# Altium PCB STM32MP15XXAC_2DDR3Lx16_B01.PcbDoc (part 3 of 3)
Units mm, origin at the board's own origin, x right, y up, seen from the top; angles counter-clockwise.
Board outline 89 x 120 mm, 4 copper layers (Top Layer, Signal Layer 1, Signal Layer 2, Bottom Layer), stack 1.571 mm thick; 152 components, 117 nets, 1047 pads, 460 vias.
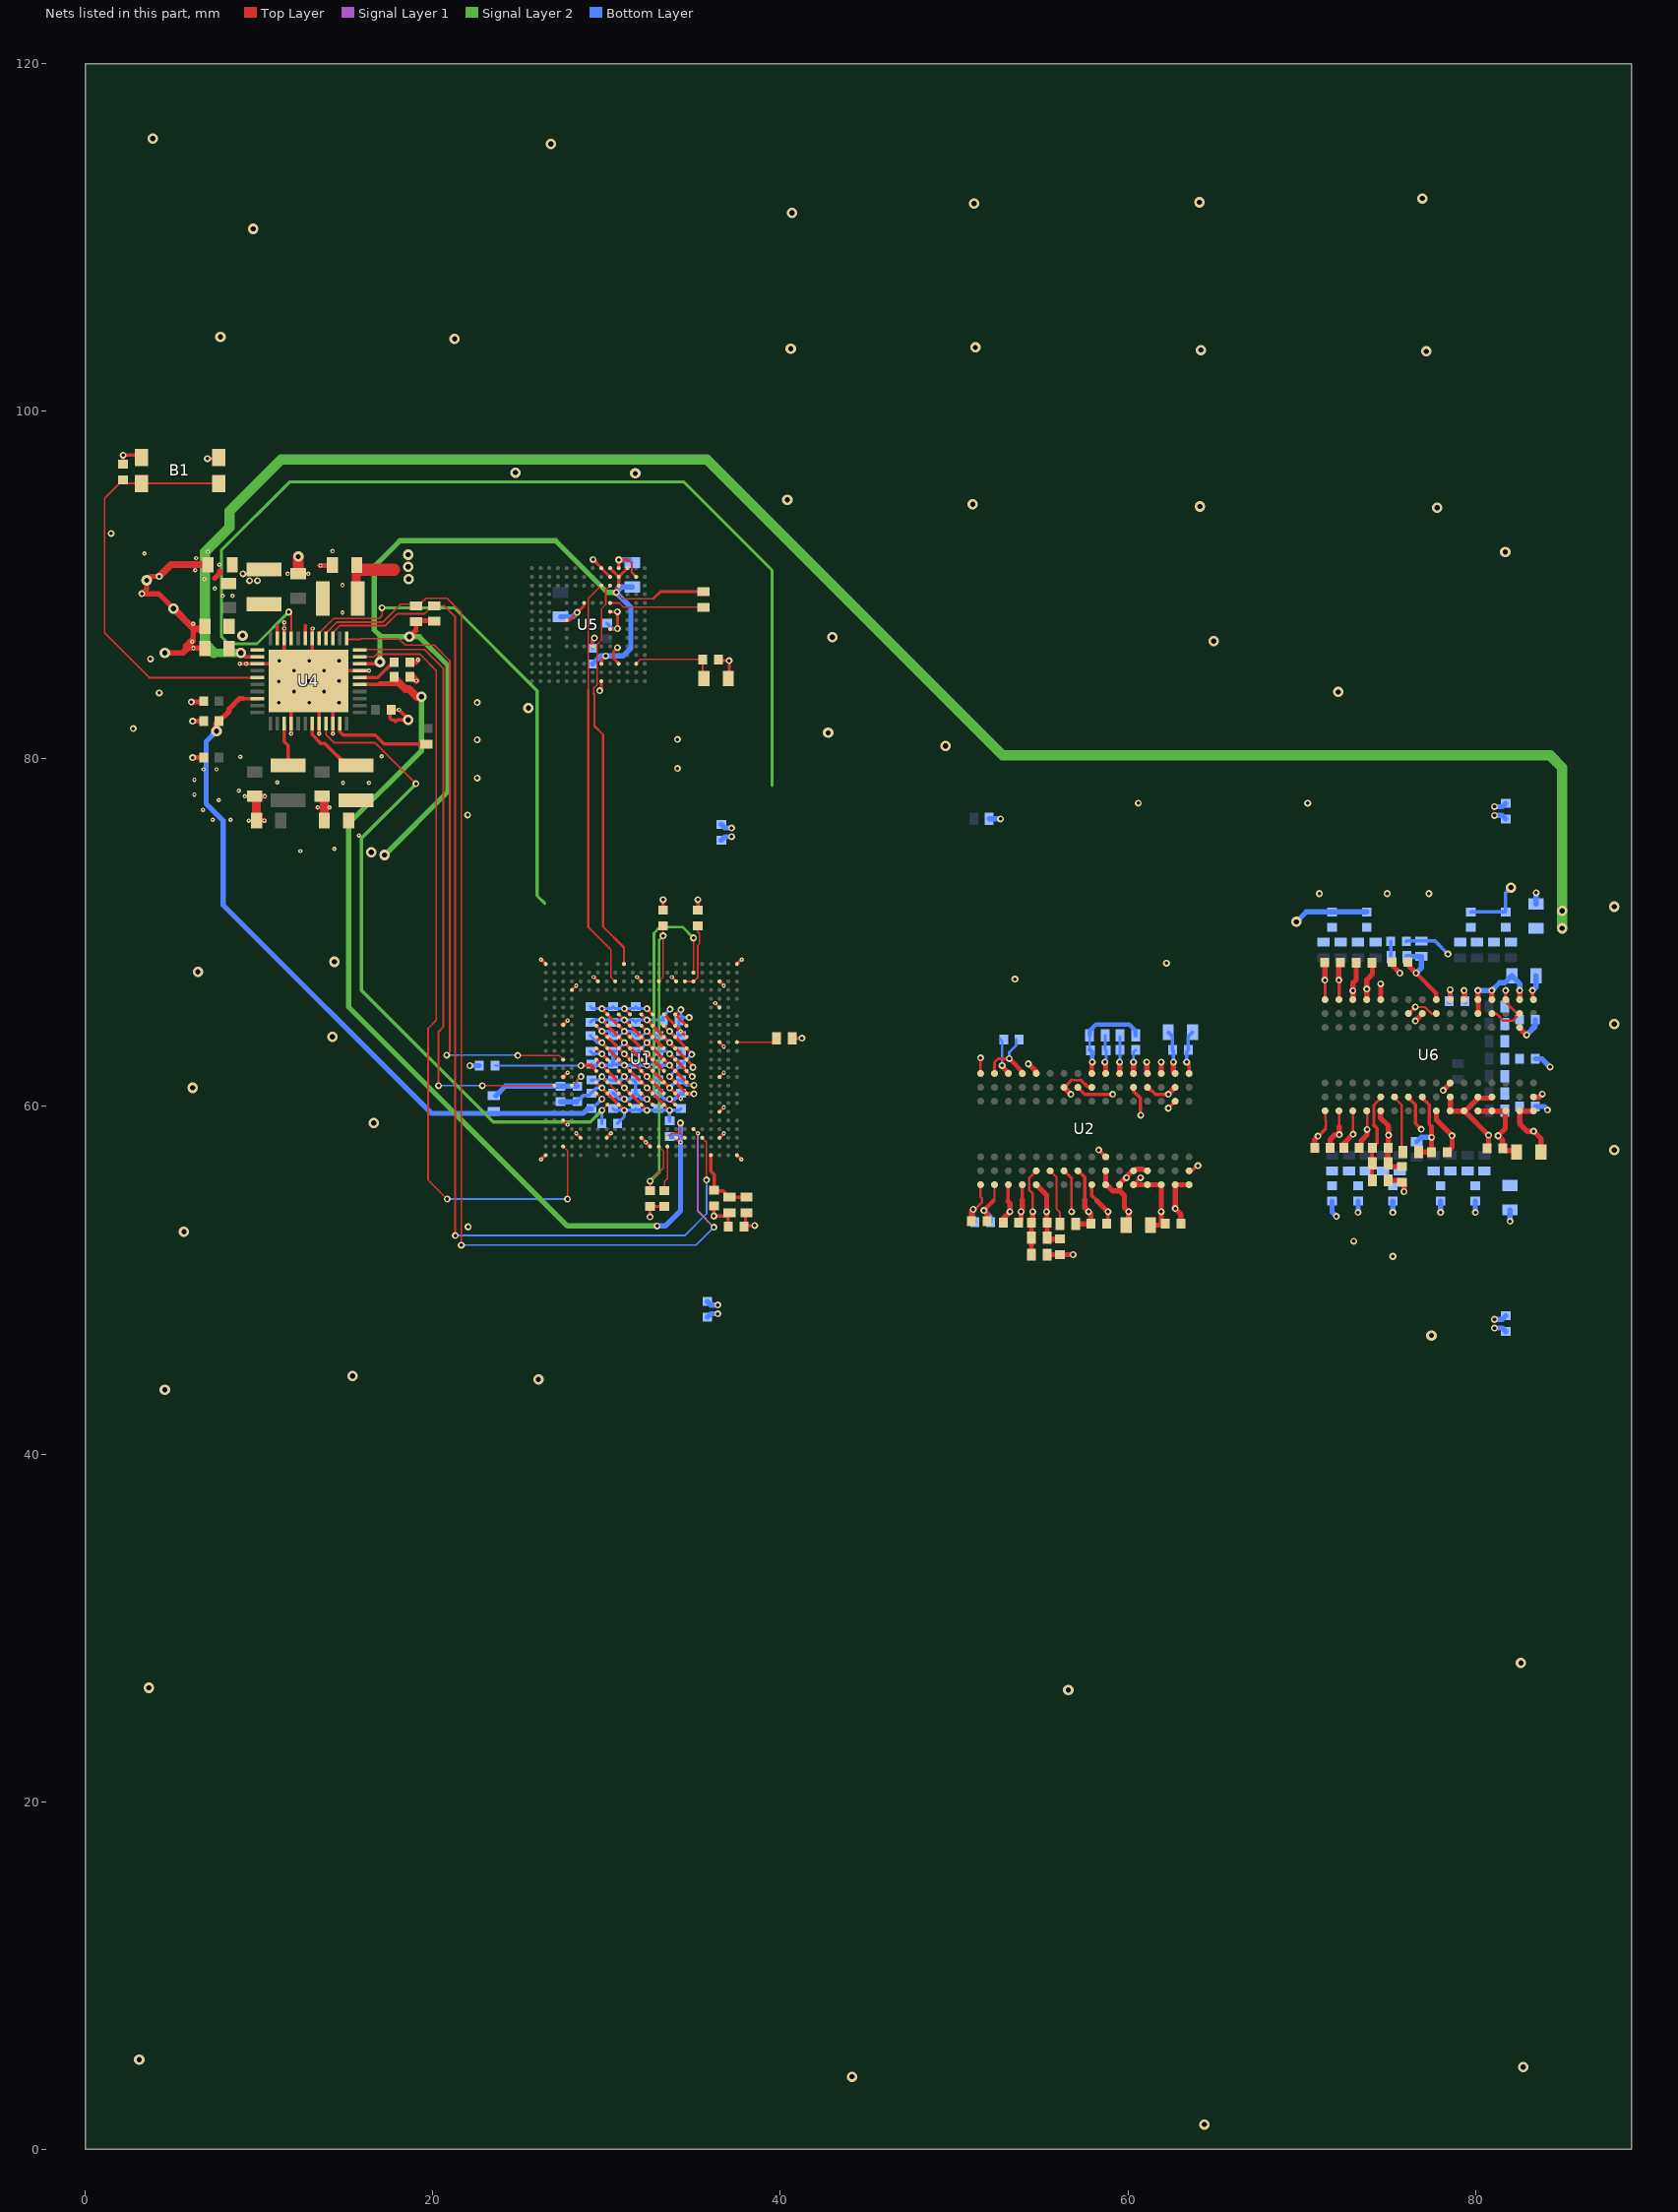
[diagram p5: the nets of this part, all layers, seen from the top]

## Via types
v1: diameter 0.4, hole 0.2, Top Layer to Bottom Layer, tented both sides, 302 vias
v2: diameter 0.6, hole 0.3, Top Layer to Bottom Layer, tented both sides, 80 vias
v3: diameter 0.25, hole 0.1, Top Layer to Signal Layer 1, tented top, 70 vias
v4: diameter 0.25, hole 0.1, Top Layer to Signal Layer 1, tented both sides, 6 vias
v5: diameter 0.25, hole 0.1, Top Layer to Bottom Layer, tented top, 2 vias

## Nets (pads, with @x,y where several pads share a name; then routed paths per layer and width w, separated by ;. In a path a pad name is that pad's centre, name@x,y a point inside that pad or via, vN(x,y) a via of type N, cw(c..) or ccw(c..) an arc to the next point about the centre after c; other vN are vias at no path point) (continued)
GND: B1.1 B1.2 C1.2 C2.2 C3.2 C4.2 C5.2 C6.2 C7.2 C8.2 C9.2 C10.2 C11.2 C12.2 C13.1 C14.1 C15.1 C16.1 C17.2 C18.1 C19.2 C20.2 C21.2 C22.2 C23.2 C24.2 C25.2 C26.2 C27.2 C28.2 C29.1 C30.1 C31.1 C32.1 C33.1 C34.1 C35.1 C36.1 C37.1 C38.1 C39.1 C40.1 C41.1 C42.1 C43.2 C44.1 C45.1 C46.1 C47.1 C48.1 C49.1 C50.1 C51.1 C52.1 C53.1 C54.1 C55.1 C56.1 C57.1 C58.1 C59.1 C60.2 C61.1 C62.2 C63.2 C64.2 C65.2 C66.1 C67.1 C68.1 C69.1 C70.1 C71.1 C72.1 C73.2 C74.2 C75.1 C76.1 C77.1 C78.1 C79.1 C80.1 C81.1 C82.1 C83.1 C84.2 C85.2 C86.2 C87.2 C88.1 C89.2 C90.2 C91.2 C92.1 C93.2 C94.1 C95.1 C96.1 C97.1 R26.1 R27.2 R28.1 R29.1 R30.1 R32.1 R42.1 R44.1 R45.1 R46.1 U1.1A3 U1.1A5 U1.1A7 U1.1B2 U1.1B4 U1.1B6 U1.1B8 U1.1C1 U1.1C3 U1.1C5 U1.1C7 U1.1C9 U1.1D2 U1.1D4 U1.1D6 U1.1D8 U1.1E1 U1.1E3 U1.1E5 U1.1E7 U1.1E9 U1.1F2 U1.1F4 U1.1F6 U1.1F8 U1.1G1 U1.1G3 U1.1G5 U1.1G7 U1.1G9 U1.1H2 U1.1H4 U1.1H6 U1.1H8 U1.1J3 U1.1J5 U1.1J7 U1.A1 U1.A23 U1.AA5 U1.AA8 U1.AA12 U1.AA16 U1.AA21 U1.AB13 U1.AC1 U1.AC23 U1.C7 U1.C12 U1.C16 U1.C21 U1.D4 U1.F21 U1.H3 U1.K21 U1.P3 U1.P21 U1.V21 U1.W3 U2.A9 U2.B1 U2.B3 U2.B9 U2.D1 U2.D8 U2.E1 U2.E2 U2.E8 U2.F9 U2.G1 U2.G8 U2.G9 U2.J2 U2.J8 U2.M1 U2.M9 U2.P1 U2.P9 U2.T1 U2.T9 U4.6 U4.10 U4.15 U4.26 U4.30 U4.32 U4.41 U4.ep U5.A6 U5.C4 U5.E7 U5.G5 U5.H10 U5.J5 U5.K8 U5.N2 U5.N5 U5.P4 U5.P6 U6.A9 U6.B1 U6.B3 U6.B9 U6.D1 U6.D8 U6.E1 U6.E2 U6.E8 U6.F9 U6.G1 U6.G8 U6.G9 U6.J2 U6.J8 U6.M1 U6.M9 U6.P1 U6.P9 U6.T1 U6.T9 | length 236.5
  Top Layer w0.09: 31.225,91.45 31.45,91.225 31.45,90.725
  Top Layer w0.12: U2.M1@54.725,61.9 U2.M1@54.725,62 ; v1(58.675,62.55) v1@58.725,62.5 ; v1@62.325,59.958 v1@62.383,59.958
  Top Layer w0.15: v1(51.105,54.08) 51.205,54.08 51.6,54.475 51.6,54.725 51.525,54.8 U2.T9@51.525,55.5 U2.T9@51.525,55.55 ; U2.T1@51.525,61.9 v1(51.525,62.8) ; v1@52.765,62.31 v1(52.765,62.36) ; v1(70.94,58.295) v1@70.975,58.295 ; U6.T1@71.36,66.085 71.36,66.15 v1@71.36,67.275 ; 71.375,58.695 71.375,58.845 71.4,58.87 71.4,59.18 71.375,59.205 U6.T9@71.375,59.75 ; v1(72.96,58.405) U6.P9@72.96,59.685 ; U6.T9@71.35,59.725 71.365,59.71 U6.T9@71.35,59.725
  Top Layer w0.175: v3(26.225,56.95) 26.475,57.2 U1.AC1@26.5,57.2 ; v3(26.225,68.45) 26.25,68.45 U1.A1@26.5,68.2 ; U1.W3@27.5,59.2 v3(27.75,58.95) ; U1.P3@27.5,61.7 v3(27.75,61.95) ; U5.H10@27.7,87.975 27.85,87.975 v1(28.3,88.425) 28.7,88.825 U5.K8@28.7,88.975 ; U1.D4@28,66.7 v3(28.25,66.95) ; v3(28.25,58.45) U1.AA5@28.5,58.2 ; v1(29.225,91.475) 29.7,91 U5.P6@29.7,90.975 U5.N5@30.2,90.475 ; v3(29.25,67.45) U1.C7@29.5,67.2 ; U1.1G1@29.4,61.4 v1(29.725,61.075) U1.1H2@30.05,60.75 U1.1J3@30.7,60.1 v1(31.025,59.775) ; U1.1E1@29.4,62.7 v1(29.725,62.375) U1.1F2@30.05,62.05 U1.1G3@30.7,61.4 v1(31.025,61.075) U1.1H4@31.35,60.75 U1.1J5@32,60.1 v1(32.325,59.775) ; U1.1C1@29.4,64 v1(29.725,63.675) U1.1D2@30.05,63.35 U1.1E3@30.7,62.7 v1(31.025,62.375) U1.1F4@31.35,62.05 U1.1G5@32,61.4 v1(32.325,61.075) U1.1H6@32.65,60.75 U1.1J7@33.3,60.1 v1(33.625,59.775) ; v1(29.6,83.925) 29.7,84.025 U5.A6@29.7,84.475 ; v1(29.725,64.975) U1.1B2@30.05,64.65 U1.1C3@30.7,64 v1(31.025,63.675) U1.1D4@31.35,63.35 U1.1E5@32,62.7 v1(32.325,62.375) U1.1F6@32.65,62.05 U1.1G7@33.3,61.4 v1(33.625,61.075) U1.1H8@33.95,60.75 33.975,60.75 v3(34.275,60.45) ; U5.G5@30.2,87.475 30.601,87.475 v1(30.625,87.5) v1(30.625,88.475) U5.J5@30.2,88.475 ; v1(30.625,86.4) 30.4,86.175 30.4,85.775 U5.C4@30.7,85.475 ; U1.1A3@30.7,65.3 v1(31.025,64.975) U1.1B4@31.35,64.65 U1.1C5@32,64 v1(32.325,63.675) U1.1D6@32.65,63.35 U1.1E7@33.3,62.7 v1(33.625,62.375) U1.1F8@33.95,62.05 U1.1G9@34.6,61.4 34.775,61.225 v1(35.025,61.225) ; U5.P4@30.7,90.948 U5.P4@30.7,90.975 v1(30.7,91.45) 31.225,91.45 ; 31.45,90.725 U5.N2@31.7,90.475 ; v3(31.75,67.45) U1.C12@32,67.2 ; U1.1A5@32,65.3 v1(32.325,64.975) U1.1B6@32.65,64.65 U1.1C7@33.3,64 v1(33.625,63.675) U1.1D8@33.95,63.35 U1.1E9@34.6,62.7 34.975,62.325 v1(34.975,62.25) ; v1(32.5,53.65) C67.1@32.5,54.25 C69.1@33.325,54.25 ; U1.1A7@33.3,65.3 U1.1B8@33.95,64.65 v3(34.275,64.325) U1.1C9@34.6,64 ; v3(33.75,67.45) U1.C16@34,67.2 ; U1.1C9@34.6,63.975 U1.1C9@34.6,64 ; U1.1C9@34.625,64 U1.1C9@34.6,64 ; v3(36.25,65.95) U1.F21@36.5,65.7 ; C82.1@36.425,85.725 36.5,85.65 v1(37.05,85.65) 37.05,84.675 C83.1@37,84.625 ; U1.AA21@36.5,58.2 v3(36.75,58.45) ; U1.V21@36.5,59.7 v3(36.75,59.95) ; U1.P21@36.5,61.7 v3(36.75,61.95) ; U1.K21@36.5,63.7 v3(36.75,63.45) ; U1.C21@36.5,67.2 v3(36.75,66.95) ; U1.AC23@37.5,57.2 v3(37.75,56.95) ; U1.A23@37.5,68.2 37.75,68.45 v3(37.775,68.45)
  Top Layer w0.2: C44.1@2.175,96.95 v1(2.175,97.475) 3.1,97.475 B1.1@3.225,97.35 ; v1(7.025,97.275) 7.6,97.275 B1.2@7.675,97.35 ; v4(8.882,85.482) 9.243,85.482 v4(9.25,85.475) U4.15@9.9,85.475 10.875,85.475 U4.ep@10.9,85.45 ; v3@11.45,87.825 v3(11.45,87.5) U4.10@11.45,86.925 11.45,85.875 12.125,85.2 v1(12.85,84.475) ; v3(11.85,81.45) U4.26@11.85,82.025 11.85,83.475 12.125,83.75 v1(12.85,84.475) ; v2(12.255,91.64) v2@12.381,91.514 ; v3@13.05,87.5 U4.6@13.05,86.925 13.05,85.65 U4.ep@13.05,84.675 ; v3@13.45,81.425 v3(13.45,81.45) U4.30@13.45,82.025 U4.ep@13.45,83.875 ; v3(14.25,81.45) U4.32@14.25,82.025 14.25,83.075 13.587,83.738 U4.ep@13.45,83.875 ; v3(16.325,85.075) U4.41@15.8,85.075 v1(13.725,85.075) 13.45,85.075 U4.ep@13.05,84.675 ; C51.1@17.537,82.762 17.537,82.338 17.625,82.25 17.757,82.25 17.857,82.15 17.957,82.25 v2(18.575,82.25) ; C51.1@17.6,82.825 v3(18.05,82.825) v2@18.6,82.275 ; U1.H3@27.5,64.7 v3(27.75,64.95) ; U5.E7@29.2,86.475 29.2,86.825 29.312,86.937 v1@29.325,86.95 ; U1.AA8@30,58.2 v3(30.25,58.45) ; U1.AA12@32,58.2 v5(32.25,57.95) U1.AB13@32.5,57.7 ; C66.1@33.25,71.3 v1(33.25,71.9) ; U1.AA16@34,58.2 v3(34.25,57.95) ; C68.1@35.25,71.3 v1(35.25,71.9) ; C72.1@36,54.275 36.087,54.188 36.175,54.1 v1(36.175,53.7) 37,53.7 C88.1@37,53.1 C88.1@37,53.05 ; R27.2@40.675,63.925 v1(41.25,63.925) ; 53.105,54.53 53.105,55.48 U2.P9@53.125,55.5 ; C26.2@55.325,53.35 C26.2@55.35,53.325 ; R44.1@55.35,52.45 R44.1@55.425,52.375 ; U2.J8@57.105,56.343 57.136,56.311 57.525,55.923 57.525,54.625 ; U2.J2@57.125,61.1 57.525,60.7 v1(59.125,60.7) ; U2.E2@60.325,61.15 U2.E2@60.325,61.1 60.325,60.88 60.725,60.48 v1@60.725,59.5 ; U2.D1@61.085,61.94 U2.D1@61.125,61.9 ; v1(61.085,62.55) v1@61.125,62.51 ; v1@62.383,59.958 U2.B3@62.725,60.3 ; U2.B1@62.625,62 U2.B1@62.725,61.9 ; v1@70.975,58.295 71.375,58.695 ; R46.1@74.975,56.725 R46.1@75.15,56.55 ; C28.2@74.975,57.625 C28.2@75,57.65 ; C27.2@75.22,68.115 C27.2@75.22,68.315 ; U6.J8@76.96,60.485 77.34,60.105 77.34,58.96 77.48,58.82 ; U6.G9@78.55,59.725 U6.G9@78.56,59.725 ; U6.G1@78.55,66.125 U6.G1@78.55,66.15 v1(78.55,66.715) ; U6.F9@79.36,59.685 79.387,59.713 79.39,59.715 U6.F9@79.38,59.725 ; C60.2@80.76,57.525 C60.2@80.82,57.465 ; U6.A9@83.32,59.725 83.323,59.723 U6.A9@83.37,59.675 ; C58.1@83.775,57.46 83.818,57.418 C58.1@83.97,57.265 ; v1(12.85,84.475) U4.ep@13.05,84.675 ; v1(12.85,84.475) U4.ep@13.45,83.875
  Top Layer w0.3: v1(4.25,90.5) 3.75,90.5 v2(3.525,90.275) 3.525,89.775 v1(3.25,89.5) 4.225,89.5 v2(5.075,88.65) ; v2(4.575,86.1) 5.65,86.1 5.675,86.125 ; v1(6.1,83.275) 6.75,83.275 C41.1@6.8,83.325 C41.1@6.775,83.35 ; v3(6.144,86.744) 5.925,86.525 5.925,86.5 ; v1(6.175,80.075) C32.1@6.8,80.075 ; v1(6.175,82.175) C49.1@6.8,82.175 ; v3(6.2,87.775) 6.2,87.525 6.2,86.95 ; C46.1@6.85,86.375 v3(6.214,86.375) 5.925,86.375 ; 7.45,90.4 7.725,90.675 7.725,90.8 ; C39.1@9.75,77.85 v3(10.325,77.85) ; C40.1@9.85,76.45 v3(10.3,76.45) ; C33.1@12.255,90.701 12.25,90.696 12.227,90.673 C33.1@12.25,90.65 C33.1@12.4,90.5 ; v3@13.5,91.125 v3(13.525,91.125) 13.95,91.125 14.075,91 C34.1@14.2,90.875 ; C43.2@18.6,85.575 18.649,85.526 C43.2@18.65,85.525 ; C43.2@18.684,85.562 19.012,85.562 v3(19.15,85.7) ; C21.2@51,53.4 51,53.975 v1(51.105,54.08) ; v1@52.765,62.31 U2.P1@53.15,61.925 ; C20.2@52.825,53.325 52.825,53.56 v1(53.215,53.95) 53.215,54.42 53.105,54.53 ; v1(54.275,62.45) U2.M1@54.725,62 ; U2.M9@54.725,55.5 55.325,54.9 v1(55.325,53.95) C26.2@55.325,53.35 ; R44.1@55.35,52.45 C26.2@55.35,53.325 ; R44.1@55.425,52.375 C90.2@56.1,52.375 ; R29.1@57,53.25 C19.2@57.875,53.25 57.875,53.81 57.74,53.945 57.525,54.16 57.525,54.625 ; U2.G9@58.725,55.5 U2.G9@58.725,55.55 ; U2.G8@58.725,56.3 U2.G9@58.725,55.55 ; U2.G1@58.725,61.9 v1@58.725,62.5 ; U2.F9@59.505,55.543 59.894,55.931 60.294,56.331 60.305,56.343 60.325,56.343 60.438,56.343 60.489,56.393 60.861,56.393 60.912,56.343 U2.D8@61.053,56.343 ; U2.F9@59.525,55.55 U2.F9@59.525,55.5 59.525,55.15 ; C15.1@59.9,53.175 60.045,53.32 60.045,53.93 60.035,53.94 59.805,54.17 59.805,54.87 59.525,55.15 ; U2.E1@60.325,61.9 v1(60.325,62.55) ; U2.D1@61.085,61.94 v1(61.085,62.55) ; U2.B1@62.625,62 v1(62.625,62.55) ; C17.2@63.05,53.25 63.05,53.8 v1(62.725,54.125) U2.B9@62.725,55.5 U2.A9@63.525,55.5 ; C74.2@70.75,57.625 70.75,58.105 v1(70.94,58.295) ; v1(71.34,67.275) C63.2@71.34,68.285 ; C73.2@72.425,57.625 72.425,57.87 v1(72.96,58.405) ; U6.P1@72.95,66.125 U6.P1@72.95,66.15 v1(72.95,66.665) 72.95,67.105 73.14,67.295 C65.2@73.14,68.275 ; U6.M9@74.55,59.725 74.55,59.33 75,58.88 v1(75,58.345) C28.2@75,57.65 ; U6.M1@74.56,66.125 74.56,66.15 v1@74.56,67.055 ; R46.1@74.975,56.725 C28.2@74.975,57.625 ; R46.1@75.15,56.55 C93.2@75.775,56.55 ; C27.2@75.22,68.115 v1(75.66,67.675) ; v1(76.55,64.925) U6.J2@76.95,65.325 ; R30.1@76.725,57.375 C62.2@77.475,57.375 ; C62.2@77.48,57.375 v1(77.48,58.225) 77.48,58.82 ; U6.G8@78.56,60.485 78.56,59.75 78.56,59.725 79.35,59.725 U6.F9@79.38,59.725 ; U6.E1@80.15,66.125 U6.E1@80.15,66.15 v1(80.15,66.675) ; U6.E2@80.16,65.325 80.16,65.35 U6.E1@80.16,66.125 ; C60.2@80.76,57.525 80.76,57.6 v1(80.76,58.345) 79.39,59.715 80.16,60.485 80.95,60.485 U6.D8@80.96,60.485 ; U6.D1@80.95,66.125 U6.D1@80.95,66.15 v1(80.95,66.675) ; U6.B3@82.55,64.51 v1(82.945,64.115) ; U6.B1@82.55,66.125 U6.B1@82.55,66.15 v1(82.55,66.675) ; U6.A9@83.32,59.725 82.55,59.725 82.55,59.005 82.98,58.575 v1(83.35,58.575) 83.775,58.15 C58.1@83.775,57.46 ; 5.675,86.125 5.675,86.25 5.863,86.438 ; 5.675,86.125 5.925,86.375 ; 5.863,86.438 5.925,86.5 ; 5.863,86.438 5.925,86.375 ; 5.863,86.438 5.775,86.525 6.069,86.819 6.2,86.95 ; 5.925,86.375 5.925,86.5 ; 5.925,86.5 6.157,86.732 6.2,86.775 6.2,86.95 ; U2.G9@58.725,55.55 58.75,55.525 59.125,55.15 59.525,55.15
  Top Layer w0.4: v1(4.25,90.5) 4.925,91.175 6.325,91.175 C29.1@7.05,91.175 ; v2(5.075,88.65) 6.075,87.65 6.2,87.525 6.25,87.475 C42.1@6.6,87.475 ; C52.1@18.751,84.801 v3(19.053,84.5)
  Top Layer w0.5: C18.1@8.125,90.1 C18.1@8.25,90.1 ; C39.1@9.75,77.85 9.85,77.75 C40.1@9.85,76.45 ; C31.1@13.625,77.85 13.625,77.75 13.75,77.625 13.75,77.2 C38.1@13.75,76.45
  Top Layer w0.6: C33.1@12.25,90.65 12.25,90.696 12.25,91.635 v2(12.255,91.64)
  Bottom Layer w0.15: C22.2@52.675,63.85 52.762,63.762 52.765,63.76 v1(52.765,62.36) ; v1(58.675,62.55) 58.75,62.625 C25.2@58.75,63.225 58.7,63.275 R42.1@58.7,64.1 ; v1(60.325,62.55) 60.325,63.125 C89.2@60.45,63.25
  Bottom Layer w0.175: C75.1@29.075,64.075 29.475,63.675 v1(29.725,63.675) 30.225,63.175 C37.1@30.375,63.175 30.525,63.175 v1(31.025,63.675) 31.525,63.175 C36.1@31.675,63.175 31.825,63.175 v1(32.325,63.675) 32.725,64.075 C45.1@32.975,64.075 33.225,64.075 v1(33.625,63.675) 34.125,63.175 C57.1@34.275,63.175 ; C35.1@29.075,64.85 29.2,64.975 v1(29.725,64.975) 30.375,64.975 v1(31.025,64.975) 31.55,64.975 C76.1@31.675,64.85 31.8,64.975 v1(32.325,64.975) C53.1@33.25,64.975 ; C96.1@30.375,59.875 C96.1@30.475,59.775 ; C47.1@30.625,59.025 31.025,59.425 v1(31.025,59.775) ; C81.1@31.325,91.45 C81.1@31.475,91.3 ; C95.1@31.575,59.775 C95.1@31.675,59.875 C95.1@31.775,59.775 ; C55.1@32.875,59.775 C55.1@32.975,59.875 C55.1@33.075,59.775 ; C53.1@33.275,64.95 C53.1@33.25,64.975 ; v1(33.65,65.6) 33.25,65.2 C53.1@33.25,64.975 ; C54.1@34.175,59.775 C54.1@34.275,59.875
  Bottom Layer w0.2: C97.1@28.3,60.35 28.3,60.275 28.312,60.287 28.65,60.625 28.975,60.625 C70.1@29.125,60.775 29.425,61.075 v1(29.725,61.075) ; C94.1@29.125,62.425 29.175,62.375 v1(29.725,62.375) 30.325,62.375 C48.1@30.375,62.425 ; C80.1@29.2,86.375 29.2,86.825 29.312,86.937 v1@29.325,86.95 ; C78.1@30.025,87.8 30.35,87.475 30.6,87.475 v1(30.625,87.5) ; C37.1@30.375,63.175 C48.1@30.375,62.425 ; C96.1@30.475,59.775 v1(31.025,59.775) C95.1@31.575,59.775 ; C92.1@31.675,62.425 C92.1@31.725,62.375 ; C95.1@31.775,59.775 v1(32.325,59.775) C55.1@32.875,59.775 ; C55.1@33.075,59.775 v1(33.625,59.775) ; C71.1@33.625,59.175 v1(33.625,59.775) ; v1(33.625,61.075) 34.075,61.525 C56.1@34.275,61.525 34.575,61.225 v1(35.025,61.225) ; v1(33.625,62.375) 33.025,62.375 C77.1@32.975,62.425 32.375,62.425 v1(32.325,62.375) C92.1@31.725,62.375 ; C54.1@34.175,59.775 v1(33.625,59.775) ; v1(51.105,54.08) 51.105,53.445 C23.2@51.2,53.35 ; C16.1@62.325,64.275 62.575,64.025 C24.2@62.575,63.25 62.625,63.2 v1(62.625,62.55) ; C91.2@75.125,69.5 75.125,68.625 R45.1@75.15,68.6 75.15,68.185 v1(75.66,67.675) ; C10.2@79.75,71.2 C9.2@81.75,71.2 81.75,72.3 v2(82.05,72.6) ; C48.1@30.375,62.425 30.975,62.425 v1(31.025,62.375) 31.675,62.375 C92.1@31.725,62.375
  Bottom Layer w0.3: v1(22.125,62.35) C61.1@22.675,62.35 ; C50.1@27.35,60.275 C97.1@28.3,60.275 ; C79.1@27.35,88.175 28.05,88.175 v1(28.3,88.425) ; v1(30.7,91.45) C81.1@31.325,91.45 ; C87.2@35.8,48.775 36,48.575 v1(36.4,48.575) ; C84.2@36.6,76.225 36.8,76.025 v1(37.2,76.025) ; R28.1@52.025,76.55 v1(52.675,76.55) ; v2(69.7,70.625) 70.275,71.2 C12.2@71.75,71.2 C11.2@73.75,71.2 ; C2.2@71.75,54.55 71.75,53.925 v1(72,53.675) ; v1(73.25,53.9) C3.2@73.25,54.55 ; v1(75.25,53.9) C4.2@75.25,54.55 ; R26.1@76.625,57.975 76.875,58.225 v1(77.48,58.225) ; v1(78,53.9) C1.2@78,54.55 ; C64.2@78.5,66.05 78.55,66.1 v1(78.55,66.715) ; v1(80,53.9) C5.2@80,54.55 ; v1(80.15,66.675) v1(80.95,66.675) 81.4,67.125 81.7,67.125 C59.1@82.1,67.525 82.55,67.075 v1(82.55,66.675) ; v1(81.1,47.75) 81.55,47.75 C86.2@81.75,47.95 ; v1(81.1,77.25) 81.55,77.25 C85.2@81.75,77.45 ; v1(82,53.4) C13.1@82,54.05 ; v1(82.945,64.115) 83.45,64.62 C8.2@83.45,65 ; C6.2@83.45,60 83.95,60 v1(84.15,59.8) ; C7.2@83.45,62.75 83.825,62.75 v1(84.3,62.275) ; C14.1@83.5,71.65 v1(83.5,72.3)
  other v1: 75.25,51.375 73,52.25 22.025,53.075 57.745,53.95 60.045,53.95 59.925,55.9 60.745,59.5 62.325,59.9 74.55,67.055 53.5,67.325 62.225,68.25 71.025,72.25 74.925,72.25 77.325,72.25 22,76.775 60.6,77.45 70.35,77.45 22.55,78.9 34.075,79.45 22.55,81.1 34.075,81.125 2.75,81.75 11.125,83.225 12.875,83.225 14.6,83.225 22.55,83.25 4.25,83.801 12,83.875 13.725,83.875 11.125,84.45 14.6,84.475 12,85.075 11.15,85.65 12.875,85.65 14.6,85.65 3.75,85.75 29.3,86.95 1.475,92.975
  other v2: 64.4,1.425 44.125,4.175 82.75,4.725 3.1,5.15 56.575,26.425 3.65,26.55 82.625,27.975 4.575,43.7 26.075,44.3 15.375,44.5 77.475,46.825 5.675,52.8 88,57.5 16.6,59.05 6.175,61.075 14.225,64 88,64.75 6.475,67.75 14.325,68.325 88,71.5 49.5,80.75 42.75,81.5 25.5,82.925 72.1,83.85 64.95,86.775 43,87 81.725,91.9 77.8,94.45 64.15,94.525 51.075,94.65 40.4,94.9 31.65,96.425 24.75,96.475 77.175,103.45 64.2,103.525 40.6,103.6 51.225,103.675 21.25,104.175 7.775,104.275 9.65,110.5 40.675,111.425 51.15,111.95 64.125,112.025 76.95,112.25 26.8,115.375 3.875,115.7
  other v3: 12.375,74.7 14.325,74.825 15.75,75.6 9.4,76.45 6.775,77.075 13.375,77.2 14.05,77.2 7.675,77.625 9.175,77.85 8.825,78.175 14.825,78.625 16.325,78.625 11.05,78.65 6.8,79.4 7.55,79.4 8.911,80.125 17.05,80.15 13.075,87.5 11.45,87.85 14.8,88.425 7.9,89.375 8.475,89.375 7.45,89.8 14.8,90 6.85,90.35 11.65,90.65 12.825,90.65 6.325,90.85 7.7,91.175 6.375,91.55 3.4,91.825 7.05,91.925 14.225,91.95
  other v4: 7.325,76.5 8.35,76.5 6.275,77.95 6.275,78.8
I2C4_SCL: R37.2 U1.Y18 U4.4 | length 66.8
  Top Layer w0.1: U4.4@13.85,86.925 13.85,87.237 14.488,87.875 17.125,87.875 18.15,88.9 19.025,88.9 19.26,88.9 19.6,89.24 20.81,89.24 21.638,88.413 v1(21.638,52.025) ; U1.Y18@35,58.7 v5(35.25,58.45)
  Signal Layer 1 w0.1: v5(35.25,58.45) 35.25,53.975 v1(36.175,53.05)
  Bottom Layer w0.1: v1(21.638,52.025) 35.15,52.025 v1(36.175,53.05)
I2C4_SDA: R38.2 U1.AA19 U4.3 | length 63.3
  Top Layer w0.09: U1.AA19@35.5,58.2 35.75,57.95 v1(35.75,55.775)
  Top Layer w0.1: U4.3@14.25,86.925 14.25,87.267 14.658,87.675 17.275,87.675 17.95,88.35 19.525,88.35 20.012,88.838 R38.2@19.975,88.875 ; R38.2@20.074,88.813 20.637,88.813 21.288,88.162 v1(21.288,52.575)
  Bottom Layer w0.1: v1(21.288,52.575) 34.5,52.575 35.75,53.825 v1(35.75,55.775)
NetB1_3: B1.3 B1.4 C44.2 U4.17 | length 24.5
  Top Layer w0.1: B1.4@7.675,95.85 B1.3@3.225,95.85 2.175,95.85 1.95,95.85 1.1,95 1.1,87.25 3.675,84.675 U4.17@9.9,84.675
NetC25_1: C25.1 R33.1 R42.2 U2.H1 | length 5.7
  Top Layer w0.25: U2.H1@57.925,61.9 57.925,62.52 v1(57.955,62.55)
  Bottom Layer w0.15: C25.1@57.8,63.275 R42.2@57.8,64.1
  Bottom Layer w0.25: C25.1@57.8,63.275 C25.1@57.85,63.225 57.955,63.12 v1(57.955,62.55) ; R42.2@57.8,64.1 57.8,64.35 58.175,64.725 60.075,64.725 60.45,64.35 R33.1@60.45,64.1
NetC26_1: C26.1 R34.1 R44.2 U2.M8 | length 5.1
  Top Layer w0.15: C26.1@54.45,53.325 C26.1@54.525,53.4 ; v1(54.525,53.95) v1@54.525,54.1 ; 54.525,54.15 54.525,54.975 54.325,55.175 54.325,55.9 U2.M8@54.725,56.3
  Top Layer w0.3: R34.1@54.45,51.475 R44.2@54.45,52.45 C26.1@54.45,53.325 ; C26.1@54.525,53.4 v1(54.525,53.95)
NetC27_1: C27.1 R35.1 R45.2 U6.H1 | length 4.8
  Top Layer w0.25: C27.1@76.12,68.145 C27.1@76.12,68.315 ; v1(76.59,67.675) 77.75,66.515 U6.H1@77.75,66.15 U6.H1@77.75,66.125
  Top Layer w0.3: C27.1@76.12,68.145 v1(76.59,67.675)
  Bottom Layer w0.3: R45.2@76.05,68.6 76.075,68.625 R35.1@76.9,68.625 76.9,67.985 v1(76.59,67.675)
NetC28_1: C28.1 R36.1 R46.2 U6.M8 | length 5.1
  Top Layer w0.15: 74.16,58.925 74.16,60.085 U6.M8@74.56,60.485
  Top Layer w0.2: R36.1@74.075,55.75 R46.2@74.075,56.725 C28.1@74.075,57.625 74.346,57.896 74.346,58.739 74.16,58.925 ; U6.M8@74.51,60.485 74.55,60.485 U6.M8@74.56,60.485
NetC43_1: C43.1 U4.40 | length 2.2
  Top Layer w0.2: U4.40@15.8,84.675 16.828,84.675 C43.1@17.689,85.536
NetC61_2: C61.2 U1.1F1 | length 6
  Top Layer w0.2: v1@28.55,62.375 29.075,62.375 U1.1F1@29.4,62.05
  Top Layer w0.3: v1@28.475,62.35 v1(28.525,62.35) v1@28.55,62.375
  Bottom Layer w0.1: C61.2@23.575,62.35 v1(28.525,62.35)
NetC68_2: C68.2 U1.C17 U1.C18 | length 3.9
  Top Layer w0.1: U1.C17@34.5,67.2 U1.C18@35,67.2 35.025,67.2 35.25,67.425 35.25,69.275 35.35,69.375 35.35,69.945 35.25,70.045 C68.2@35.25,70.4
NetC69_2: C69.2 U1.AB15 | length 2.6
  Top Layer w0.09: C69.2@33.325,55.15 33.325,55.675 33.5,55.85 U1.AB15@33.5,57.7
NetC72_2: C72.2 R31.1 R32.2 U1.AC20 | length 4.1
  Top Layer w0.2: U1.AC20@36,57.2 36,56.275 36.2,56.075 36.2,55.175 36.2,55.15 36.7,55.15 R32.2@37.075,54.775 R31.1@38.05,54.775
NetC82_2: C82.2 C83.2 U5.C2 | length 5.1
  Top Layer w0.09: U5.C2@31.7,85.475 31.95,85.725 32.7,85.725
  Top Layer w0.1: 32.7,85.725 C82.2@35.525,85.725 35.525,84.7 C83.2@35.6,84.625
NetL1_1: L1.1 U4.7 | length 0.7
  Top Layer w0.2: U4.7@12.65,86.925 12.65,87.672
NetL2_1: L2.1 U4.11 | length 0.7
  Top Layer w0.2: U4.11@11.05,86.925 11.05,87.65
NetL3_1: L3.1 U4.29 | length 3.9
  Top Layer w0.2: U4.29@13.05,82.025 13.05,81.39 13.565,80.875 13.8,80.875 15.05,79.625 L3.1@15.575,79.625
NetL4_1: L4.1 U4.25 | length 2.4
  Top Layer w0.2: U4.25@11.45,82.025 11.45,81 11.675,80.775 L4.1@11.675,79.725
NetR27_1: R27.1 U1.K23 | length 2.3
  Top Layer w0.09: U1.K23@37.5,63.7 39.75,63.7 R27.1@39.775,63.725
NetR29_2: R29.2 U2.L8 | length 3.3
  Top Layer w0.12: U2.L8@55.525,56.3 55.9,55.925 55.9,54.1 56.1,53.9 R29.2@56.1,53.25 R29.2@56.1,53.225
NetR30_2: R30.2 U6.L8 | length 3.3
  Top Layer w0.12: U6.L8@75.36,60.485 75.76,60.085 75.76,57.44 R30.2@75.825,57.375
NetR40_1: R40.1 U5.K5 | length 5.5
  Top Layer w0.09: 30.725,88.975 30.975,88.725 R40.1@35.575,88.725
  Top Layer w0.1: U5.K5@30.2,88.975 30.725,88.975
NetR43_1: R43.1 U4.33 | length 5.7
  Top Layer w0.2: U4.33@14.65,82.025 14.65,81.561 14.836,81.375 16.675,81.375 17.2,80.85 R43.1@19.625,80.85
NRST: U1.M3 U4.1 | length 36
  Top Layer w0.09: v1(24.89,62.94) 27.26,62.94 U1.M3@27.5,62.7
  Top Layer w0.1: U4.1@15.05,86.875 15.82,86.875 15.87,86.925 18.025,86.925 18.4,86.55 20.075,86.55 20.975,85.65 20.975,63.125 v1(20.8,62.95)
  Bottom Layer w0.09: v1(20.8,62.95) 24.88,62.95 v1(24.89,62.94)
PA0_WKUP: U1.AB3 U4.43 | length 46
  Top Layer w0.09: U1.AB3@27.5,57.7 27.75,57.45 v1(27.75,54.675)
  Top Layer w0.1: U4.43@15.8,85.875 16.614,85.875 16.764,86.025 19.25,86.025 20.2,85.075 20.2,64.975 19.725,64.5 19.725,55.775 v1(20.825,54.675)
  Bottom Layer w0.1: v1@20.8,54.675 v1(20.825,54.675) v1(27.75,54.675)
PWR_ON: U1.R2 U4.44 | length 36.1
  Top Layer w0.09: v1@22.825,61.2 v1(22.85,61.2) U1.R2@27,61.2
  Top Layer w0.1: U4.44@15.85,86.225 15.925,86.3 19.525,86.3 20.6,85.225 20.6,64.575 20.325,64.3 v1(20.325,61.2)
  Bottom Layer w0.09: v1(20.325,61.2) v1(22.85,61.2)
SDMMC2_CK: U1.C9 U5.M6 | length 23.7
  Top Layer w0.09: 28.95,84 28.95,89.225 U5.M6@29.7,89.975 ; 30.137,69.138 30.25,69.025 30.25,67.45 U1.C9@30.5,67.2
  Top Layer w0.13: 28.95,84 28.95,70.325 30.137,69.138
SDMMC2_CMD: U1.A10 U5.M5 | length 22.9
  Top Layer w0.09: 29.255,83.745 29.255,84.068 29.46,84.273 29.46,86.574 29.7,86.814 29.7,88.636 29.95,88.886 29.95,89.725 U5.M5@30.2,89.975 ; U1.A10@31,68.2 31,69.15
  Top Layer w0.13: 29.255,83.745 29.3,83.7 29.3,81.9 29.8,81.4 29.8,70.35 31,69.15
VDD: C38.2 C47.2 C48.2 C80.2 C81.2 C92.2 C94.2 C95.2 C96.2 L3.2 R37.1 R38.1 R40.2 U1.1F3 U1.1G2 U1.1G4 U1.1H3 U1.1H5 U1.1J2 U1.1J4 U1.1J6 U1.B18 U4.31 U4.42 U5.C6 U5.M4 U5.N4 U5.P3 U5.P5 | length 120.2
  Top Layer w0.09: v1(30.55,89.575) 30.9,89.225 32.7,89.225 ; U1.B18@35,67.7 v1(35,69.7) v1@35,69.8
  Top Layer w0.1: U4.31@13.85,82.025 13.85,81.4 14.325,80.925 16.675,80.925 v1(19.025,78.575)
  Top Layer w0.12: v1(29.725,59.775) U1.1J2@30.05,60.1 ; v1(29.725,61.725) U1.1G2@30.05,61.4 U1.1H3@30.7,60.75 v1(31.025,60.425) U1.1J4@31.35,60.1 ; U1.1F3@30.7,62.05 v1(31.025,61.725) U1.1G4@31.35,61.4 ; U1.1H5@32,60.75 v1(32.325,60.425) U1.1J6@32.65,60.1
  Top Layer w0.175: U5.C6@29.7,85.475 29.7,85.675 v1(29.95,85.925) ; U5.P5@30.2,90.975 U5.N4@30.7,90.475 ; v1(30.55,89.575) 30.55,89.825 U5.M4@30.7,89.975 U5.N4@30.7,90.475 ; U5.P3@31.2,90.975 U5.N4@30.7,90.475 ; 32.7,89.225 33.1,89.625 R40.2@35.575,89.625
  Top Layer w0.2: U4.42@15.8,85.475 v2@16.85,85.475 ; v2@16.85,85.475 v2(16.95,85.575) ; v2@16.85,85.475 v2(16.95,85.575) ; v2(16.95,85.575) 16.95,85.579 v2(16.95,85.575) v2(16.95,85.575)
  Top Layer w0.25: 19,87.375 19.025,87.4 R37.1@19.025,87.9
  Top Layer w0.3: v2@18.65,87.15 v2(18.65,87.025) 19,87.375 ; R37.1@19.325,87.95 20.074,87.95 R38.1@20.175,87.95
  Signal Layer 2 w0.15: 32.6,60.675 32.725,60.8 32.725,69.975 33.075,70.325 34.375,70.325 v1(35,69.7)
  Signal Layer 2 w0.2: 16.95,87.1 17.025,87.025 ; v1(19.025,78.575) 15.9,75.45 15.9,66.675 23.475,59.1 29.05,59.1 v1(29.725,59.775)
  Signal Layer 2 w0.3: v2(16.95,85.575) 16.95,87.1 16.625,87.425 16.625,91.075 18.1,92.55 27.075,92.55 30.05,89.575 v1(30.55,89.575) ; 17.025,87.025 v2(18.65,87.025) 19.225,87.025 20.875,85.375 20.875,78.125 v2(17.225,74.475)
  Bottom Layer w0.09: C48.2@30.375,61.525 C48.2@30.4,61.5
  Bottom Layer w0.175: C47.2@29.725,59.025 v1(29.725,59.775)
  Bottom Layer w0.2: C94.2@29.125,61.525 29.525,61.525 v1(29.725,61.725) 29.925,61.525 C48.2@30.375,61.525 ; C96.2@30.375,60.775 30.725,60.425 v1(31.025,60.425) 31.325,60.425 C95.2@31.675,60.775 ; C48.2@30.4,61.5 30.8,61.5 v1(31.025,61.725) 31.225,61.525 C92.2@31.675,61.525 C95.2@31.675,60.775 ; v1(32.325,60.425) 32.025,60.425 C95.2@31.675,60.775
  Bottom Layer w0.3: C80.2@29.2,85.475 29.65,85.925 v1(29.95,85.925) 30.95,85.925 31.4,86.375 31.4,88.725 v1(30.55,89.575) 30.875,89.9 C81.2@31.475,89.9
  other v2: 16.45,74.625
VDD_CORE: C30.2 C34.2 C35.2 C36.2 C37.2 C75.2 C76.2 C77.2 L1.2 U1.1A2 U1.1A4 U1.1A6 U1.1B1 U1.1B3 U1.1B5 U1.1C2 U1.1C4 U1.1C6 U1.1D1 U1.1D3 U1.1D5 U1.1D7 U1.1E2 U1.1E4 U1.1E6 U1.1F5 U1.1F7 U1.1G6 U1.1H7 U4.5 | length 54.1
  Top Layer w0.1: U4.5@13.45,86.925 13.45,87.237 14.288,88.075 16.9,88.075 17.075,88.25 v1(17.075,88.7)
  Top Layer w0.175: U1.1D1@29.4,63.35 v1(29.725,63.025) U1.1E2@30.05,62.7 ; U1.1B1@29.4,64.65 v1(29.725,64.325) U1.1C2@30.05,64 U1.1D3@30.7,63.35 v1(31.025,63.025) U1.1E4@31.35,62.7 U1.1F5@32,62.05 v1(32.325,61.725) U1.1G6@32.65,61.4 U1.1H7@33.3,60.75 ; v1(29.725,65.625) U1.1A2@30.05,65.3 U1.1B3@30.7,64.65 v1(31.025,64.325) U1.1C4@31.35,64 U1.1D5@32,63.35 v1(32.325,63.025) U1.1E6@32.65,62.7 U1.1F7@33.3,62.05 ; v1(31.025,65.625) U1.1A4@31.35,65.3 ; U1.1B5@32,64.65 v1(32.325,64.325) U1.1C6@32.65,64 U1.1D7@33.3,63.35 ; v1(32.325,65.625) U1.1A6@32.65,65.3
  Top Layer w0.5: C34.2@15.6,90.875 15.6,89.3 L1.2@15.675,89.225
  Top Layer w0.7: C34.2@15.675,90.875 17.775,90.875
  Signal Layer 2 w0.175: v1(17.075,88.7) 21.225,88.7 26,83.925 26,72.125 26.45,71.675
  Bottom Layer w0.175: C75.2@29.075,63.175 29.225,63.025 v1(29.725,63.025) ; C35.2@29.075,65.75 29.2,65.625 v1(29.725,65.625) 30.25,65.625 C30.2@30.375,65.75 30.5,65.625 v1(31.025,65.625) 31.55,65.625 C76.2@31.675,65.75 31.8,65.625 v1(32.325,65.625) ; v1(29.725,64.325) 30.125,64.325 C37.2@30.375,64.075 30.775,64.075 v1(31.025,64.325) 31.425,64.325 C36.2@31.675,64.075 32.075,64.075 v1(32.325,64.325)
  Bottom Layer w0.2: v1(32.325,61.725) 32.525,61.525 C77.2@32.975,61.525
  other v2: 18.6,90.35 18.575,91.05 18.575,91.75
VDD_DDR: C15.2 C16.2 C17.1 C19.1 C20.1 C21.1 C22.1 C23.1 C24.1 C29.2 C42.2 C45.2 C53.2 C54.2 C55.2 C56.2 C57.2 C58.2 C59.2 C60.1 C62.1 C63.1 C64.1 C65.1 C73.1 C74.1 C84.1 C85.1 C86.1 C87.1 C88.2 C89.1 C90.1 C91.1 C93.1 L2.2 R31.2 R33.2 R34.2 R35.2 R36.2 U1.1A8 U1.1B7 U1.1B9 U1.1C8 U1.1D9 U1.1E8 U1.1F9 U1.1G8 U1.1H9 U1.1J8 U2.A1 U2.A8 U2.B2 U2.C1 U2.C9 U2.D2 U2.D9 U2.E9 U2.F1 U2.G7 U2.H2 U2.H9 U2.K2 U2.K8 U2.N1 U2.N9 U2.R1 U2.R9 U4.9 U4.13 U6.A1 U6.A8 U6.B2 U6.C1 U6.C9 U6.D2 U6.D9 U6.E9 U6.F1 U6.G7 U6.H2 U6.H9 U6.K2 U6.K8 U6.N1 U6.N9 U6.R1 U6.R9 | length 146.3
  Top Layer w0.1: v1(11.7,88.45) 11.85,88.3 U4.9@11.85,86.925
  Top Layer w0.12: 52.265,54.57 52.325,54.63 U2.R9@52.325,55.5 U2.R9@52.325,55.55 ; U2.C1@61.88,61.889 U2.C1@61.905,61.914 ; v1(76.55,65.725) 77.1,65.725 77.5,65.325 U6.H2@77.75,65.325 ; U6.A1@83.29,66.185 83.338,66.138 U6.A1@83.35,66.125
  Top Layer w0.15: U2.R1@52.325,61.9 52.325,62.55 52.525,62.75 v1(53.175,62.75) v1@53.255,62.67 ; 56.75,55.875 56.75,53.955 56.76,53.945 v1@56.765,53.94 ; 56.75,61.525 57.3,61.525 ; v1@72.16,58.385 v1(72.17,58.375) ; 72.16,58.825 U6.R9@72.16,59.685 ; C73.1@73.325,57.625 C73.1@73.425,57.725 ; v1(73.77,58.675) U6.N9@73.77,59.675 ; U6.D2@80.95,65.325 81.22,65.325 81.375,65.17 81.595,64.95 82.175,64.95 82.55,65.325 82.44,65.325 U6.C1@81.75,66.015
  Top Layer w0.175: U1.1B7@33.3,64.65 v1(33.625,64.325) U1.1C8@33.95,64 U1.1D9@34.6,63.35 34.9,63.05 v1(34.9,63) ; v1(33.625,60.425) U1.1J8@33.95,60.1 ; v1(33.625,61.725) U1.1G8@33.95,61.4 U1.1H9@34.6,60.75 35,60.75 v1(35.025,60.725) ; v1(33.625,63.025) U1.1E8@33.95,62.7 U1.1F9@34.6,62.05 v1(34.925,61.725) ; v1(34.275,65.575) 34.225,65.575 U1.1A8@33.95,65.3 U1.1B9@34.6,64.65 U1.1B9@34.6,64.625 ; C88.2@37.9,53.05 37.925,53.075 C88.2@38,53.15 ; R31.2@38.05,53.875 38,53.825 C88.2@38,53.15 ; v1(38.525,53.15) C88.2@38,53.15
  Top Layer w0.2: C20.1@53.725,53.325 C20.1@53.855,53.455 ; 53.925,54.645 U2.N9@53.925,55.5 ; U2.K8@56.325,56.35 U2.K8@56.325,56.3 56.75,55.875 ; U2.K2@56.325,61.1 56.75,61.525 ; 57.3,61.525 57.675,61.15 U2.H2@57.925,61.15 ; U2.H9@57.925,55.5 57.925,54.87 58.22,54.575 ; U2.H9@57.925,55.55 U2.H9@57.955,55.55 ; v1(58.325,57.5) U2.G7@58.725,57.1 ; C19.1@58.775,53.25 58.855,53.33 v1@58.855,53.94 ; U2.E9@60.325,55.5 v1(60.725,55.9) ; U2.E9@60.325,55.55 U2.E9@60.325,55.593 ; U2.D2@61.105,61.114 61.125,61.114 61.133,61.114 U2.D2@61.105,61.143 ; U2.D2@61.125,61.1 61.305,60.92 61.382,60.92 61.602,60.7 v1(62.325,60.7) ; U2.B2@62.705,61.138 U2.B2@62.705,61.143 ; v1(63.385,62.55) 63.525,62.41 U2.A1@63.525,61.9 ; U2.A8@63.525,56.3 63.685,56.3 63.985,56.6 63.995,56.59 v1(64.035,56.59) ; C63.1@72.14,68.185 C63.1@72.24,68.285 ; U6.R1@72.16,66.125 72.16,66.15 v1@72.16,67.275 ; C65.1@74.04,68.275 C65.1@74.08,68.235 ; C93.1@75.675,55.75 C93.1@75.775,55.65 ; U6.K2@76.15,65.325 76.162,65.338 v1(76.55,65.725) ; U6.K8@76.16,60.485 76.55,60.095 76.55,59.025 v1(76.89,58.685) ; U6.C9@81.72,59.695 U6.C9@81.75,59.725 ; U6.C1@81.75,66.015 U6.C1@81.75,66.15 v1(81.75,66.675) ; C58.2@82.37,57.465 82.418,57.418 C58.2@82.57,57.265 ; U6.A1@83.29,66.185 v1(83.29,66.675)
  Top Layer w0.25: v1(51.715,54.02) 52.265,54.57 ; v1@53.255,62.67 53.925,62 U2.N1@53.925,61.9
  Top Layer w0.3: v1(51.715,54.02) 51.9,53.835 C21.1@51.9,53.4 ; C20.1@53.855,53.455 v1(53.855,53.95) 53.925,54.02 53.925,54.645 ; R34.2@55.35,51.475 C90.1@56.1,51.475 v1(56.85,51.475) ; U2.K2@56.325,61.1 v1(56.725,60.7) ; 58.22,54.575 58.85,53.945 v1@58.855,53.94 ; U2.F1@59.525,61.9 v1@59.525,62.51 ; U2.E9@60.325,55.5 U2.D9@61.125,55.5 U2.C9@61.925,55.5 v1(61.925,53.95) 61.925,53.25 61.925,53.225 61.875,53.175 ; C15.2@61.3,53.175 61.875,53.175 ; U2.C1@61.925,61.9 v1@61.925,62.5 ; C17.1@62.15,53.25 62.075,53.175 61.875,53.175 ; v1(62.325,60.7) U2.B2@62.725,61.1 ; C74.1@71.65,57.625 71.65,58.1 71.925,58.375 v1(72.17,58.375) 72.17,58.815 72.16,58.825 ; v1(72.14,67.275) C63.1@72.14,68.185 ; C73.1@73.425,57.725 73.425,58.025 73.77,58.37 v1(73.77,58.675) ; v1(73.75,66.765) 73.75,67.285 74.08,67.615 C65.1@74.08,68.235 ; U6.N1@73.75,66.125 U6.N1@73.75,66.15 v1(73.75,66.765) ; R36.2@74.975,55.75 C93.1@75.675,55.75 ; C93.1@75.775,55.65 75.9,55.525 v1(75.9,55.1) ; U6.H9@77.76,59.685 77.76,59.225 v1(78.66,58.325) 78.66,57.66 C62.1@78.375,57.375 ; v1(78.15,60.925) U6.G7@78.55,61.325 ; U6.F1@79.35,66.125 U6.F1@79.35,66.15 v1(79.35,66.675) ; U6.E9@80.15,59.725 80.95,59.725 U6.C9@81.75,59.725 ; C60.1@81.575,57.6 81.575,58.04 v1(81.3,58.315) 81.72,58.735 U6.C9@81.72,59.695 ; C60.1@81.72,57.465 C58.2@82.37,57.465 ; U6.A8@83.35,60.525 83.66,60.525 v1(83.85,60.715)
  Signal Layer 2 w0.175: v1(11.7,88.45) 9.875,86.625 8.25,86.625 7.825,87.05 7.825,92 11.775,95.95 31.436,95.95 31.448,95.937 31.852,95.937 31.864,95.95 34.425,95.95 39.525,90.85 39.525,78.475
  Bottom Layer w0.15: v1(53.175,62.75) 53.175,63.125 53.575,63.525 C22.1@53.575,63.85 ; v1(59.525,62.55) 59.55,62.575 C89.1@59.55,63.25 R33.2@59.55,64.025
  Bottom Layer w0.175: C45.2@32.975,63.175 33.475,63.175 v1(33.625,63.025) 33.898,62.752 33.973,62.752 34.275,62.45 C56.2@34.275,62.425 ; v1(33.625,61.725) C56.2@34.275,62.375 ; v1(33.625,64.325) 33.875,64.075 C57.2@34.275,64.075 34.175,64.175 C53.2@34.175,64.95 C53.2@34.275,65.05 ; C54.2@34.275,60.775 C54.2@34.325,60.725 ; v1(34.275,65.575) C53.2@34.275,65.05 ; v1(34.75,65.125) 34.35,65.125 C53.2@34.275,65.05 ; v1(34.9,63) 34.325,62.425 C56.2@34.275,62.425 ; v1(34.925,61.725) C56.2@34.275,62.375 ; C56.2@34.275,62.375 C56.2@34.275,62.425
  Bottom Layer w0.2: C55.2@32.975,60.775 33.325,60.425 v1(33.625,60.425) 33.925,60.425 C54.2@34.275,60.775 ; C54.2@34.325,60.725 v1(35.025,60.725) ; v1(51.715,54.02) 51.78,54.02 52.1,53.7 C23.1@52.1,53.35 ; v1(63.385,62.55) 63.385,63.16 C24.1@63.475,63.25 63.475,64.025 C16.2@63.725,64.275 ; C91.1@76.025,69.5 76.05,69.525 R35.2@76.9,69.525 77.675,69.525 v1(78.425,68.775)
  Bottom Layer w0.3: C87.1@35.8,47.875 36,48.075 v1(36.4,48.075) ; C84.1@36.6,75.325 36.8,75.525 v1(37.2,75.525) ; v1(79.35,66.675) 79.35,66.1 C64.1@79.4,66.05 ; v1(81.1,47.25) 81.55,47.25 C86.1@81.75,47.05 ; v1(81.1,76.75) 81.55,76.75 C85.1@81.75,76.55 ; v1(83.29,66.675) 83.5,66.885 C59.2@83.5,67.525
  other v1: 56.765,53.95 58.855,53.95 61.925,62.55 9.45,90.25 9.9,90.25 9.075,90.65
  other v2: 9.05,87.1
VDD_USB: C52.2 C71.2 U1.AA15 U1.AA17 U4.39 | length 57.9
  Top Layer w0.09: U1.AA15@33.5,58.2 33.75,58.45 34.25,58.45 ; v1@34.25,59.125 v1(34.25,59.05) 34.25,58.45 ; U1.AA17@34.5,58.2 34.25,58.45
  Top Layer w0.2: U4.39@15.8,84.275 16.85,84.275 ; C52.2@17.625,84.575 C52.2@17.775,84.725 C52.2@17.775,84.66 ; 16.85,84.275 18.075,84.275 18.117,84.317 18.175,84.375 18.059,84.375 17.775,84.375 16.95,84.375 16.85,84.275
  Top Layer w0.45: C52.2@17.775,84.66 17.775,84.659 18.059,84.375 18.117,84.317 18.409,84.025 18.625,84.025 19.075,83.575 v2(19.35,83.575)
  Signal Layer 2 w0.3: v2(19.35,83.575) 19.35,80.475 15.15,76.275 15.15,65.725 27.75,53.125 v1(32.9,53.125)
  Bottom Layer w0.09: 34.225,58.275 34.25,58.25
  Bottom Layer w0.3: v1(32.9,53.125) 33.375,53.125 34.25,54 34.25,58.25 v1(34.25,59.05) ; C71.2@33.625,58.275 34.225,58.275
VDDA: C49.2 C70.2 R41.1 U1.1H1 U4.20 | length 41.4
  Top Layer w0.09: U1.1H1@29.4,60.75 v1(29.725,60.425)
  Top Layer w0.2: 9.075,83.475 U4.20@9.9,83.475
  Top Layer w0.3: C49.2@7.7,82.175 8.275,82.75 8.275,82.873 8.55,83.148 8.55,83.155 8.87,83.475 9.075,83.475
  Top Layer w0.4: v2(7.55,81.6) 7.55,82.025 C49.2@7.7,82.175
  Bottom Layer w0.2: C70.2@29.35,60.05 v1(29.725,60.425)
  Bottom Layer w0.3: v2(7.55,81.6) 6.95,81 6.95,77.425 7.925,76.45 7.925,71.6 19.925,59.6 23.5,59.6 28.65,59.6 28.925,59.875 C70.2@29.125,59.875
VDDA_1V8: C66.2 C67.2 U1.AB14 U1.C14 | length 20.7
  Top Layer w0.09: C67.2@32.5,55.15 v1(32.5,55.7) 33.275,56.475 33.275,57.425 U1.AB14@33,57.7
  Top Layer w0.1: U1.C14@33,67.2 33.25,67.45 v1(33.25,69.825) C66.2@33.25,70.4
  Signal Layer 2 w0.1: v1@33.25,69.8 v1(33.25,69.825)
  Signal Layer 2 w0.15: 33.025,56.225 33.025,69.575 v1@33.25,69.8
  Signal Layer 2 w0.2: v1(32.5,55.7) 33.025,56.225
VREF+: C50.2 C97.2 R41.2 U1.R4 | length 6.5
  Top Layer w0.1: U1.R4@28,61.2 28.025,61.2 28.537,61.713 v1@28.575,61.75
  Bottom Layer w0.1: R41.2@23.5,60.625 R41.2@23.625,60.625 ; C97.2@28.3,61.175 28.3,61.5 v1(28.525,61.725)
  Bottom Layer w0.3: R41.2@23.625,60.625 24.175,61.175 C50.2@27.35,61.175 C97.2@28.3,61.175
VTT_DDR: C1.1 C2.1 C3.1 C4.1 C5.1 C6.1 C7.1 C8.1 C9.1 C10.1 C11.1 C12.1 C13.2 C14.2 C46.2 R1.2 R2.2 R3.2 R4.2 R5.2 R6.2 R7.2 R8.2 R9.2 R10.2 R11.2 R12.2 R13.2 R15.2 R16.2 R17.2 R18.2 R19.2 R20.2 R21.2 R22.2 R23.2 R24.2 R25.2 U4.14 | length 105.8
  Top Layer w0.2: 9.175,85.875 U4.14@9.9,85.875
  Signal Layer 2 w0.5: 7.4,86.1 v2(8.95,86.1)
  Signal Layer 2 w0.6: 7.4,86.1 6.875,86.625 6.875,91.9 8.3,93.325 8.3,94.25 11.275,97.225 35.775,97.225 52.8,80.2 84.3,80.2 85,79.5 v2(85,71.25) v2(85,70.25)
pads on no net: U1.A2 U1.A3 U1.A4 U1.A5 U1.A7 U1.A8 U1.A14 U1.A16 U1.A17 U1.A19 U1.A20 U1.AA1 U1.AA2 U1.AA3 U1.AA4 U1.AA6 U1.AA7 U1.AA9 U1.AA10 U1.AA11 U1.AA13 U1.AA14 U1.AA18 U1.AB1 U1.AB2 U1.AB4 U1.AB5 U1.AB6 U1.AB7 U1.AB8 U1.AB9 U1.AB10 U1.AB11 U1.AB12 U1.AB16 U1.AB17 U1.AB18 U1.AB19 U1.AC2 U1.AC3 U1.AC4 U1.AC5 U1.AC7 U1.AC8 U1.AC10 U1.AC11 U1.AC13 U1.AC14 U1.AC16 U1.AC17 U1.AC19 U1.B1 U1.B2 U1.B3 U1.B4 U1.B5 U1.B6 U1.B7 U1.B8 U1.B9 U1.B14 U1.B15 U1.B16 U1.B17 U1.B19 U1.B20 U1.C1 U1.C2 U1.C3 U1.C4 U1.C5 U1.C6 U1.C8 U1.C10 U1.C15 U1.C19 U1.C20 U1.D1 U1.D2 U1.D3 U1.D5 U1.D6 U1.D7 U1.D8 U1.D9 U1.D10 U1.D11 U1.D12 U1.D13 U1.D14 U1.D15 U1.D16 U1.D17 U1.D18 U1.D19 U1.E1 U1.E2 U1.E3 U1.E4 U1.F2 U1.F3 U1.F4 U1.G1 U1.G2 U1.G3 U1.G4 U1.H1 U1.H2 U1.H4 U1.J2 U1.J3 U1.J4 U1.K1 U1.K2 U1.K3 U1.K4 U1.K20 U1.L1 U1.L2 U1.L3 U1.L4 U1.L21 U1.M2 U1.M4 U1.N1 U1.N2 U1.N3 U1.N4 U1.P1 U1.P2 U1.P4 U1.P20 U1.R3 U1.T1 U1.T2 U1.T3 U1.T4 U1.U1 U1.U2 U1.U3 U1.U4 U1.V2 U1.V3 U1.V4 U1.W1 U1.W2 U1.W4 U1.Y1 U1.Y2 U1.Y3 U1.Y4 U1.Y5 U1.Y6 U1.Y7 U1.Y8 U1.Y9 U1.Y10 U1.Y11 U1.Y12 U1.Y13 U1.Y14 U1.Y15 U1.Y16 U1.Y17 U1.Y19 U2.J1 U2.J9 U2.L1 U2.L9 U2.M7 U4.2 U4.16 U4.18 U4.21 U4.23 U4.34 U4.35 U4.38 U5.A1 U5.A2 U5.A7 U5.A8 U5.A9 U5.A10 U5.A11 U5.A12 U5.A13 U5.A14 U5.B1 U5.B7 U5.B8 U5.B9 U5.B10 U5.B11 U5.B12 U5.B13 U5.B14 U5.C1 U5.C3 U5.C5 U5.C7 U5.C8 U5.C9 U5.C10 U5.C11 U5.C12 U5.C13 U5.C14 U5.D1 U5.D2 U5.D3 U5.D4 U5.D12 U5.D13 U5.D14 U5.E1 U5.E2 U5.E3 U5.E5 U5.E8 U5.E9 U5.E10 U5.E12 U5.E13 U5.E14 U5.F1 U5.F2 U5.F3 U5.F10 U5.F12 U5.F13 U5.F14 U5.G1 U5.G2 U5.G3 U5.G10 U5.G12 U5.G13 U5.G14 U5.H1 U5.H2 U5.H3 U5.H5 U5.H12 U5.H13 U5.H14 U5.J1 U5.J2 U5.J3 U5.J12 U5.J13 U5.J14 U5.K1 U5.K2 U5.K3 U5.K6 U5.K7 U5.K10 U5.K12 U5.K13 U5.K14 U5.L1 U5.L2 U5.L3 U5.L12 U5.L13 U5.L14 U5.M1 U5.M2 U5.M3 U5.M7 U5.M8 U5.M9 U5.M10 U5.M11 U5.M12 U5.M13 U5.M14 U5.N1 U5.N3 U5.N6 U5.N7 U5.N8 U5.N9 U5.N10 U5.N11 U5.N12 U5.N13 U5.N14 U5.P1 U5.P2 U5.P7 U5.P8 U5.P9 U5.P10 U5.P11 U5.P12 U5.P13 U5.P14 U6.J1 U6.J9 U6.L1 U6.L9 U6.M7

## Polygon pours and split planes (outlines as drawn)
VDD_DDR on Signal Layer 2 "VDD_DDR" (solid, remove dead copper, pour order 86): 33.2,90.475 31.025,92.65 13.15,92.65 10.3,89.8 10.3,87.475 9.625,86.8 8.475,86.8 8.125,87.15 8.125,91.775 11.85,95.5 28.475,95.5 33.825,95.5 39,90.325 39,78.75 84,78.75 84,45.5 33.2,45.5
GND on Signal Layer 2 "NETR16_2_L04_P-001" (solid, pour order 192): 24.25,58.5 29.25,58.5 29.75,59 32.25,59 32.25,56.5 32,56.25 32,54.25 31.5,53.75 28.25,53.75 24.25,57.75
GND on Signal Layer 2 "NETR16_2_L04_P-001" (solid, pour order 190): 20.25,88 21.25,88 25.5,83.75 25.5,66 25.25,65.75 25,65.75 24.5,66.25 19.5,74.75 22,77.25 22,85.5 20.25,87.25
GND on Signal Layer 2 "NETR16_2_L04_P-001" (solid, pour order 188): 40.5,90.25 40.5,79.5 51.25,79.5 51.5,79.75 41,90.25
GND on Signal Layer 2 "GND_L03_P186" (solid, remove dead copper, pour order 186): 89,68 86.5,68 86.5,82 53,82 36,99 11,99 8,96 2,96 2,75 14,75 14,65 27,52 32,52 32,44 85.5,44 85.5,68 89,68 89,44 89,0 0,0 0,120 89,120
VDD_CORE on Signal Layer 2 "VDD_CORE" (solid, remove dead copper, pour order 94): 26.225,84.05 20.775,89.5 18.1,89.5 18.1,92.3 26.475,92.3 29.375,89.4 32.725,86.048 32.725,61.409 31.65,61.409 31.65,62.025 31.156,62.5 26.225,62.5
VDD on Signal Layer 2 "VDD" (solid, remove dead copper, pour order 88): 16.126,74.8 16.126,74.751 16.126,74.625 16.126,71.05 23.625,59.475 32.75,59.475 32.75,60.841 31.114,62.375 25.907,62.375 18.355,75.025 16.274,75.025 16.126,74.9
5V_VIN on Signal Layer 2 "5V_VIN" (solid, remove dead copper, pour order 96): 17.65,85.3 17.65,84.775 19.3,84.775 19.3,79.825 15.4,75.925 2.95,75.925 2.95,94.275 7.9,94.275 7.9,85.225 11.325,85.225 11.325,90.7 16.325,90.7 16.325,85.3
GND on Top Layer "GND_L01_P182" (solid, remove dead copper, pour order 182): 86.5,68.25 86.5,65 89,65 89,120 0,120 0,45.675 0,0 89,0 89,65 86.5,65 86.5,58.5 84.5,56.5 80.25,56.5 80.25,55 79.5,54.25 71.75,54.25 71,53.5 71,51.25 65,45.25 43.25,45.25 38.25,50.25 38.25,54.5 37.6,55.15 36.6,55.15 35.25,56.5 35.225,56.475 25.775,56.475 25.5,56.75 25.5,68.5 25.75,68.75 29.25,68.75 29.25,69.25 28.25,70.25 28.25,83.75 25,83.75 25,91.5 25.25,91.75 32.5,91.75 32.75,91.5 32.75,86.5 34.25,85 34.25,72.5 33.75,72 33.75,69 34,68.75 35.5,68.75 42,75.25 79.5,75.25
5V_VIN on Top Layer "NO TR" (solid, pour order 162): 8.675,89.05 7.588,89.05 6.475,89.95 6.475,90.15 5.7,90.15 5.7,88.425 5.85,88.275 8.6,88.275 10.35,86.525 10.75,86.525 10.75,87.45 9.875,88.325 9.35,88.325
5V_VIN on Top Layer "NO TR" (solid, remove dead copper, pour order 180): 12.35,88.125 12.35,88.4 13.025,89.075 13.025,90.125 12.925,90.225 11.675,90.225 11.5,90.05 11.5,89.1 12.15,88.45 12.15,88.125
3V3 on Top Layer "NO TR" (solid, remove dead copper, pour order 178): 11.75,74.55 12.725,75.525 12.725,78.15 10.625,78.15 10.625,75.9 10.45,75.725 9.725,75.725 9.725,74.675 9.85,74.55
5V_VIN on Top Layer "NO TR" (solid, remove dead copper, pour order 176): 3.675,92.675 7.275,92.675 7.675,93.075 7.675,93.6 7.275,94 4.775,94 4.275,93.5 3.8,93.5 3.55,93.25 3.55,92.8
VDD_CORE on Top Layer "NO TR" (solid, remove dead copper, pour order 174): 17.5,89.95 17.5,91.564 18.063,92.127 18.748,92.127 19.05,91.825 19.05,89.925 18.9,89.775 17.675,89.775
VDD on Top Layer "NO TR" (solid, remove dead copper, pour order 172): 14.55,78.1 17.25,78.1 17.875,77.475 17.875,74.35 17.525,74 16.6,74 16.1,74.5 16.1,75.95 14.55,75.95
NetL4_1 on Top Layer "NO TR" (solid, remove dead copper, pour order 170): 11.325,81.575 11.35,81.6 11.55,81.6 11.575,81.575 11.575,81.3 12.725,80.153 12.725,79.225 12.675,79.175 10.675,79.175 10.625,79.225 10.625,79.975 11.325,80.675
5V_VIN on Top Layer "NO TR" (solid, remove dead copper, pour order 168): 10.925,81.575 10.95,81.6 11.15,81.6 11.175,81.575 11.175,80.725 10.5,80.05 10.5,78.475 7.95,78.475 7.775,78.65 7.775,79.025 7.9,79.15 8.825,79.15 9.175,79.5 9.438,79.75 9.701,79.75 9.75,79.801 9.75,80.338 10.925,81.451
5V_VIN on Top Layer "NO TR" (solid, remove dead copper, pour order 166): 14.425,78.575 14.325,78.475 13.075,78.475 13,78.55 13,80.075 12.525,80.55 12.525,81.575 12.55,81.6 12.75,81.6 12.775,81.575 12.775,81.293 14.425,79.656
NetL3_1 on Top Layer "NO TR" (solid, remove dead copper, pour order 164): 12.925,81.575 12.95,81.6 13.15,81.6 13.175,81.575 13.175,81.425 13.375,81.225 13.775,81.225 14.4,80.6 16.575,80.6 16.625,80.55 16.625,79.225 16.575,79.175 15.125,79.175 14.575,79.175 14.525,79.225 14.525,79.75 12.925,81.35
VDD_DDR on Top Layer "NO TR" (solid, pour order 160): 10.3,86.45 10.3,86.175 9.475,86.175 8.525,87.125 7.95,87.125 7.9,87.175 7.9,88.075 7.975,88.15 8.6,88.15
VTT_DDR on Top Layer "NO TR" (solid, remove dead copper, pour order 158): 9.7,85.775 7.875,85.775 7.7,85.95 7.7,86.7 7.875,86.875 8.65,86.875 9.075,86.45 9.55,85.975 9.7,85.975
NetL2_1 on Top Layer "NO TR" (solid, remove dead copper, pour order 156): 9.95,88.45 9.225,88.45 9.1,88.575 9.1,89.35 9.2,89.45 11.175,89.45 11.325,89.3 11.325,87.8 11.15,87.45 11.15,87.375 10.95,87.375 10.95,87.45
VDD_DDR on Top Layer "NO TR" (solid, remove dead copper, pour order 154): 11.3,91.3 10.85,91.75 8.2,91.75 7.975,91.525 7.975,90.125 8.075,90.025 9.525,90.025 10.8,90.025 11.3,90.525
NetL1_1 on Top Layer "NO TR" (solid, remove dead copper, pour order 114): 12.75,87.1 12.75,87.575 13.3,88.125 14.05,88.125 14.325,88.4 14.325,90.35 14.15,90.525 13.25,90.525 13.1,90.375 13.1,88.975 12.55,88.425 12.55,87.1
GND on Bottom Layer "GND_L04_P184" (solid, remove dead copper, pour order 184): 89,68.737 86.5,68.737 86.5,72.487 83.75,72.487 83.75,71.487 79.25,71.487 79.25,71.987 73.75,71.987 73.75,71.437 70.25,71.437 70.25,68.237 56.25,68.237 55,66.987 52,66.987 52,78.487 51.5,78.987 38.75,78.987 37.75,77.987 37.75,68.862 35.575,66.687 27.7,66.687 27.5,66.487 27.5,58.737 28.25,57.987 35,57.987 35,52.987 36.5,51.487 36.5,46.487 37.5,45.487 53.5,45.487 54.5,46.487 54.5,52.237 55,52.737 66.25,52.737 67.75,54.237 83.5,54.237 83.5,64.487 86.5,64.487 86.5,68.737 89,68.737 89,0 0,0 0,99.487 0,99.737 0,120 89,120
VTT_DDR on Bottom Layer "VTT_DDR_BOT" (solid, remove dead copper, pour order 81): 78,69.25 78,70 74.77,70 74.77,69.25 70.75,69.25 70.75,70.5 74.25,70.5 74.25,71.25 78.75,71.25 78.75,70.5 84.25,70.5 84.25,71.75 85.75,71.75 85.75,65.5 82.75,65.5 82.75,55.25 77.5,55.25 77.5,54.75 75.75,54.75 75.75,55.25 71,55.25 71,56.5 81.5,56.5 81.5,66.5 84,66.5 84,69.25
GND on Signal Layer 1 "GND" (solid, remove dead copper, pour order 104): 0.408,119.592 89,119.592 89,0.408 0.408,0.408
